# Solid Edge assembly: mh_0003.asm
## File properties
Title: magic_hand
Author: edge
Template: normal.asm
Last saved by: edge
Revision: 67
Application: Solid Edge
文書内容のタイプ: 1
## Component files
mh_0010.asm
mh_0012.asm
mh_0011.asm
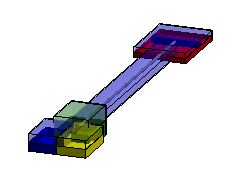
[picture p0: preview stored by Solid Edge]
